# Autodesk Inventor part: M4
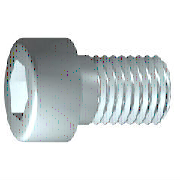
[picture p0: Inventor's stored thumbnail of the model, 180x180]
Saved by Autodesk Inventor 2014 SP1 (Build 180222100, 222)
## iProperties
IsCustomPart: 0
Created: 2016-04
Part Number: M4
Material: 강철, 연강
Description: 6각머리 태핑 나사
Document SubType Name: Modeling
Standard: KS B 1003
Designer: mdu
Standards Organization: KS
Language: ko-KR
Size Designation: M 4 x 10
Categories: <MemberInstance><Categories><Category DisplayName="조임쇠" InternalName="e4da775c-781d-43d5-af7c-5136215cf5a6" Mnemonic="FSTN"><Category DisplayName="볼트" InternalN
Density: 7.86 g/cm^3
Mass: 2.0371 g
Surface Area: 3.0572 cm^2
Volume: 0.259174 cm^3
Appearance: 금속 1800F 열
Author: mdu
Revision Number: 1
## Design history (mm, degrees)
sketch "스케치1"
  geometry: L1 (-1, 0)-(10, 0); L2 (10, 0)-(10, 2); L3 (10, 2)-(1.75, 2); L4 (1.75, 2)-(1.32, 2); L5 (1.32, 2)-(0, 2); L6 (0, 2)-(0, 3.5); L7 (0, 3.5)-(-4, 3.5); L8 (-4, 3.5)-(-4, 1.732); L9 (-4, 1.732)-(-2, 1.732); L10 (-2, 1.732)-(-1, 0); L11 (-6.8, 0)-(12.8, 0) reference; L12 (0, -0.7)-(0, 4.2) reference; L13 (1.75, 2)-(0, 2)
  constraints: 22 end point, 6 parallel, 2 collinear, 2 perpendicular, 1 horizontal, 1 point on line
  dimensions: "d1" = 8.25 distance from line of L3.end L2 (= GEL); "d2" = 0.42952 distance of L4.end L3.end (computed from GAL); "d3" = 4 distance between parallel lines of L8 L6 (= KOH); "d4" = 2 distance of L8.end L9.end (= INTI); "d5" = 60 deg angle of L10 L1; "d6" = 4 diameter of L3 L1 (= GD); "d7" = 4 diameter of L5 L1 (= BDM); "d8" = 3.4641 diameter of L9 L1 (= 1.1547 x SW); "d9" = 7 diameter of L7 L1 (= KOD); "d26" = 10 distance between parallel lines of L12 L2 (= NLG)
revolve "본체" sketch "스케치1" stored, may be unused: angle "d10" = 90 deg
sketch "스케치2"
  geometry: L1 (0, -4.9)-(0, 4.9) reference; L2 (-4.9, 0)-(4.9, 0) reference; L3 (1.732, 0)-(0.866, -1.5); L4 (0.866, -1.5)-(-0.866, -1.5); L5 (-0.866, -1.5)-(-1.732, 0); L6 (-1.732, 0)-(-0.866, 1.5); L7 (-0.866, 1.5)-(0.866, 1.5); L8 (0.866, 1.5)-(1.732, 0); 2 further points
  constraints: 12 end point, 1 coincident, 1 horizontal alignment, 1 point on line, 12 other
extrude "슬롯" join sketch "스케치2" stored distance "d11" = 10; taper "d12" = 0 deg
workplane "Work Plane1"
fillet "Fillet2" dims "d30" = 0.1 (= R)
body "Solid1"
fillet "모깎기1" dims "d17" = 0.4 (= RR)
feature "스레드" dims "d13" = 8.25 (= GEL), "d14" = 0
chamfer "모따기1" distance "d15" = 0.42941 (= -0.5 x SPD + 0.5 x GD); stored, may be unused: second distance "d16" = 0.42941 (= GUL), angle "d27" = 45 deg
other parameters: "GD" = 4 (= NND) [user parameter; used in 2 equation terms], "NLG" = 10 [user parameter; used in 1 equation term], "GEL" = 8.25 [user parameter; used in 2 equation terms], "KOD" = 7 [user parameter; used in 1 equation term], "KOH" = 4 [user parameter; used in 1 equation term], "INTI" = 2 [user parameter; used in 1 equation term], "GAL" = 0.42941 (= 0.61345 x PTC) [user parameter; used in 1 equation term], "GUL" = 0.42941 (= 0.61345 x PTC) [user parameter; used in 1 equation term], "BDM" = 4 (= NND) [user parameter; used in 1 equation term], "SW" = 3 [user parameter; used in 2 equation terms], "RR" = 0.4 [user parameter; used in 1 equation term], "SPD" = 3.14117 (= NND - 1.2269 x PTC) [user parameter; used in 1 equation term], "d19" = 0, "d28" = 0, "d29" = 0, "R" = 0.1 [user parameter; used in 1 equation term], "PHH" = 0.2 [user parameter], "GD1" = 3.14117 (= THREADDIA - 1.2269 x PTC) [user parameter], "THREADDIA" = 4 [user parameter; used in 1 equation term], "FAWI" = 45 deg [user parameter], "TPU" = 14.28571 (computed from PTC) [user parameter], "PTC" = 0.7 [user parameter; used in 5 equation terms], "NND" = 4 [user parameter; used in 3 equation terms], "TOA" = 30 deg [user parameter], "E0" = 3.465 (= 1.155 x SW) [user parameter]
